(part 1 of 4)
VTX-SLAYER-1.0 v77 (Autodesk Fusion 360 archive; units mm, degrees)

design "VTX-SLAYER-1.0" references "nut", "M2 screw size FLAT WASHER", "M2 x 0.4mm Thread 20mm LONG SOCKET HEAD CAP SCREW", "runcam_phoenix_2", "M3 x 0.5mm Thread 16mm LONG SOCKET HEAD CAP SCREW", "motor", "M2 x 0.4mm Thread 5mm LONG SOCKET HEAD CAP SCREW", "prop", "M3 x 0.5mm Thread 8mm LONG SOCKET HEAD CAP SCREW", "M2 x 0.4mm Thread HEX NUT", "M2 x 0.4mm Thread 6mm LONG SOCKET HEAD CAP SCREW"
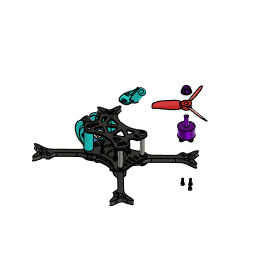
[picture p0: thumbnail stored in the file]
parameter "d278" = 4.1
parameter "d427" = 3.1
parameter "d437" = 4.2
parameter "d451" = 2.2
parameter "d614" = 15
parameter "d1109" = 4
parameter "d1134" = 12.8 (= "25.6 mm / 2.0")
canvas "Ansichtsbereich"
sketch "Skizze1" plane through (0, 0, 0) normal (0, 0, 1) x axis (1, 0, 0)
  line L1 (5.8693, -34.9991) -> (5.8693, -25.0204)
  line L2 (-57.0019, 8.0109) -> (-57.5891, 7.9385)
  line L3 (-57.259, 10.0951) -> (-57.8463, 10.0227)
  line L4 (-53.0046, 14.7338) -> (-53.0363, 15.3314)
  line L5 (-50.9075, 14.8451) -> (-50.9392, 15.4427)
  line L6 (-45.7643, 10.7703) -> (-46.3634, 10.7515)
  line L7 (-46.2975, 8.6525) -> (-45.6984, 8.6714)
  line L8 (0.8693, -39.9991) -> (-14.9589, -39.9991)
  line L9 (5.2623, -39.9991) -> (0.8693, -39.9991)
  line L10 (5.8693, -39.9991) -> (5.2623, -39.9991)
  line L11 (5.8693, -34.9991) -> (5.8693, -39.9991)
  line L12 (15.8693, -49.9991) -> (15.873, -49.9991)
  line L13 (15.8693, -29.9991) -> (15.873, -29.9991)
  line L14 (-7.6307, -25.3947) -> (-7.6307, -34.4991)
  curve K1 (-7.6307, -25.3947) -> (-10.9746, -20.0338)
  curve K2 (-12.5574, -19.204) -> (-9.3918, -20.8636)
  curve K3 (-7.6307, -25.7698) -> (-7.6307, -25.0196)
  line L15 (-20.2292, -25.643) -> (-53.829, 7.2456)
  line L16 (-49.632, 11.5333) -> (-16.0322, -21.3552)
  curve K4 (-25.1132, -12.4665) -> (-14.076, -18.1856)
  curve K5 (-42.6895, -3.6581) -> (-58.4159, 4.3179)
  curve K6 (-39.5769, 1.6911) -> (-43.0511, 12.8356)
  curve K7 (-39.0355, 1.1612) -> (-40.1182, 2.221)
  curve K8 (-42.3474, 12.2194) -> (-43.7548, 13.4517)
  curve K9 (-41.833, -4.4965) -> (-43.5461, -2.8197)
  curve K10 (-57.742, 4.1664) -> (-59.0898, 4.4693)
  curve K11 (-26.2747, -11.3295) -> (-23.9517, -13.6034)
  curve K12 (-14.6037, -17.8994) -> (-13.5483, -18.4717)
  curve K13 (-26.9801, -19.0351) -> (-22.3176, -27.7327)
  curve K14 (-22.9195, -27.2509) -> (-21.7157, -28.2145)
  curve K15 (-27.6566, -18.3729) -> (-26.3035, -19.6973)
  line L17 (-65.0703, 8.0734) -> (-57.1305, 9.053)
  line L18 (-52.3801, 22.7782) -> (-51.956, 14.7895)
  curve K16 (5.8693, -25.0204) -> (-14.076, -18.1856)
  curve K17 (-12.5184, -19.0318) -> (-15.6337, -17.3393)
  curve K18 (10.1662, -25.0241) -> (1.5724, -25.0168)
  curve K19 (-22.3176, -27.7327) -> (-10.6307, -34.4991)
  curve K20 (-10.6307, -32.2321) -> (-10.6307, -36.7662)
  curve K21 (-17.5546, -29.5) -> (-14.0454, -29.5)
  curve K22 (-23.5931, -26.7897) -> (-21.042, -28.6757)
  curve K23 (-43.0511, 12.8356) -> (-47.6742, 16.5575)
  curve K24 (-47, 15.6) -> (-48.3483, 17.515)
  curve K25 (-42.3474, 12.2194) -> (-43.7548, 13.4517)
  curve K26 (-47.6742, 16.5575) -> (-58.4159, 4.3179)
  curve K27 (-62.844, 5.395) -> (-53.9878, 3.2408)
  curve K28 (-65.2846, 9.8103) -> (-64.856, 6.3366)
  curve K29 (-54.7508, 15.3088) -> (-57.8176, 12.0705)
  curve K30 (-50.6326, 22.871) -> (-54.1277, 22.6854)
  curve K31 (-46.4995, 14.804) -> (-48.8488, 18.311)
  circle C1 centre (-51.7305, 9.3895) radius 2.7
  circle C2 centre (-57.7177, 8.9806) radius 1.05
  circle C3 centre (-57.1305, 9.053) radius 1.05
  circle C4 centre (-51.9878, 15.3871) radius 1.05
  circle C5 centre (-51.956, 14.7895) radius 1.05
  circle C6 centre (-46.3305, 9.702) radius 1.05
  circle C7 centre (-45.7313, 9.7208) radius 1.05
  circle C8 centre (-18.1307, -23.4991) radius 1.55
  circle C9 centre (-4.1307, -29.9991) radius 1.05
  circle C10 centre (15.873, -29.9991) radius 1.05
  circle C11 centre (29.8693, -23.4991) radius 1.55
  circle C12 centre (5.8693, -39.9991) radius 5
  circle C13 centre (-18.1307, -56.4991) radius 1.55
  circle C14 centre (15.873, -49.9991) radius 1.05
  circle C15 centre (29.8693, -56.4991) radius 1.55
  circle C16 centre (-4.1307, -49.9991) radius 1.05
  circle C17 centre (-9.1307, -34.4991) radius 1.5
  circle C18 centre (-18.1307, -23.4991) radius 3
  circle C19 centre (-51.7305, 9.3895) radius 3
  point P12 (-57.0019, 8.0109)
  point P11 (-57.5891, 7.9385)
  point P14 (-57.259, 10.0951)
  point P13 (-57.8463, 10.0227)
  point P15 (-53.0363, 15.3314)
  point P18 (-50.9075, 14.8451)
  point P19 (-46.3634, 10.7515)
  point P20 (-45.7643, 10.7703)
  point P21 (-45.6984, 8.6714)
  point P22 (-46.2975, 8.6525)
  point P17 (-50.9392, 15.4427)
  point P16 (-53.0046, 14.7338)
  point P29 (0.8693, -39.9991)
  point P30 (5.8693, -34.9991)
  point P24 (-18.1307, -23.4991)
  point P27 (29.8693, -23.4991)
  point P28 (5.8693, -39.9991)
  point P32 (5.8693, -39.9991)
  point P34 (15.873, -49.9991)
  point P36 (15.873, -49.9991)
  point P26 (15.873, -29.9991)
  point P38 (15.873, -29.9991)
  point P41 (-10.6307, -34.4991)
  point P43 (-9.1307, -34.4991)
  point P44 (-7.6307, -34.4991)
  point P46 (-10.9746, -20.0338)
  point P45 (-7.6307, -25.3947)
  point P49 (-7.6307, -25.7698)
  point P52 (-53.829, 7.2456)
  point P53 (-20.2292, -25.643)
  point P54 (-16.0322, -21.3552)
  point P55 (-49.632, 11.5333)
  point P23 (-14.076, -18.1856)
  point P56 (-14.076, -18.1856)
  point P57 (-25.1132, -12.4665)
  point P58 (-42.6895, -3.6581)
  point P59 (-39.5769, 1.6911)
  point P61 (-39.0355, 1.1612)
  point P86 (-43.0511, 12.8356)
  point P65 (-41.833, -4.4965)
  point P85 (-58.4159, 4.3179)
  point P69 (-26.2747, -11.3295)
  point P73 (-26.9801, -19.0351)
  point P72 (-22.3176, -27.7327)
  point P77 (-27.6566, -18.3729)
  point P6 (-57.1305, 9.053)
  point P81 (-57.1305, 9.053)
  point P8 (-51.956, 14.7895)
  point P83 (-51.956, 14.7895)
  point P7 (-51.9878, 15.3871)
  point P5 (-57.7177, 8.9806)
  point P78 (-65.0703, 8.0734)
  point P82 (-65.0703, 8.0734)
  point P80 (-52.3801, 22.7782)
  point P84 (-52.3801, 22.7782)
  point P4 (5.8693, -25.0204)
  point P42 (-15.8, -29.5)
  point P97 (-47.6742, 16.5575)
  point P79 (-56.2842, 13.6897)
  point P112 (-10.9746, -20.0338)
  point P70 (-13.5483, -18.4717)
  point P62 (-43.7548, 13.4517)
  point P100 (-43.7548, 13.4517)
  point P25 (-4.1307, -29.9991)
  point P39 (15.8693, -29.9991)
  point P2 (-51.7305, 9.3895)
  point P9 (-46.3305, 9.702)
  point P37 (15.8693, -49.9991)
  point P40 (-4.1307, -49.9991)
  point P3 (-14.9589, -39.9991)
  point P104 (-64.856, 6.3366)
  point P105 (-65.2846, 9.8103)
  point P108 (-54.1277, 22.6854)
  point P109 (-50.6326, 22.871)
  horizontal L8
  perpendicular L1 L8
  coincident C3 P12
  tangent C3 L2
  coincident C2 P11
  tangent C2 L2
  coincident C3 P14
  tangent C3 L3
  coincident C2 P13
  tangent C2 L3
  coincident C4 P15
  tangent C4 L4
  tangent C5 L4
  coincident C5 P18
  tangent C5 L5
  tangent C4 L5
  coincident C6 P19
  tangent C6 L6
  coincident C7 P20
  tangent C7 L6
  coincident C7 P21
  tangent C7 L7
  coincident C6 P22
  tangent C6 L7
  coincident C4 P17
  coincident C5 P16
  coincident C12 P29
  coincident C12 P30
  perpendicular L1 L9
  horizontal P24 P27
  parallel L9 L10
  perpendicular L9 L11
  coincident P28 P32
  symmetric C8 L8 C13
  symmetric C10 L8 C14
  symmetric C11 L8 C15
  coincident P34 P36
  coincident P26 P38
  parallel L12 L13
  symmetric C9 L8 C16
  coincident P41 C17
  horizontal P41 P43
  coincident C17 P44
  tangent C17 L14
  vertical L14
  midpoint P46 K2
  midpoint P45 K3
  coincident L14 P49
  concentric C8 C18
  concentric C1 C19
  coincident C19 P52
  coincident C18 P53
  tangent C18 L15
  coincident C18 P54
  coincident C19 P55
  tangent C19 L16
  tangent C19 L15
  tangent C18 L16
  coincident P23 P56
  coincident L16 P57
  coincident L15 P58
  coincident L16 P59
  midpoint P59 K7
  coincident L16 P61
  parallel L16 K7
  midpoint K8 P86
  midpoint P58 K9
  coincident L15 P65
  parallel L15 K9
  midpoint K10 P85
  midpoint P57 K11
  coincident L16 P69
  midpoint P56 K12
  coincident L15 P73
  midpoint P72 K14
  midpoint P73 K15
  coincident L15 P77
  parallel L15 K15
  coincident P6 P81
  coincident P8 P83
  coincident P7 L18
  coincident P5 L17
  coincident P78 P82
  coincident P80 P84
  midpoint P23 K17
  midpoint P4 K18
  midpoint P41 K20
  midpoint P42 K21
  midpoint P72 K22
  midpoint P97 K24
  midpoint P86 K25
  midpoint P85 K27
  midpoint P78 K28
  midpoint P79 K29
  midpoint P80 K30
  midpoint P97 K31
  coincident P46 P112
  coincident P70 K16
  perpendicular L17 K28
  perpendicular L18 K30
  coincident P62 P100
  dimension "d4" diameter C1 = 5.4
  dimension "d8" diameter C2 = 2.1
  dimension "d9" diameter C3 = 2.1
  dimension "d10" diameter C4 = 2.1
  dimension "d11" diameter C5 = 2.1
  dimension "d12" diameter C6 = 2.1
  dimension "d13" diameter C7 = 2.1
  dimension "d14" diameter C8 = 3.1
  dimension "d16" diameter C9 = 2.1
  dimension "d17" diameter C10 = 2.1 (= "d16")
  dimension "d20" diameter C11 = 3.1 (= "d14")
  dimension "d23" distance P25 P39 = 20
  dimension "d27" diameter C12 = 10
  dimension "d50" distance P4 P28 = 14.9787
  dimension "d58" distance P24 P27 = 48 (= "d103 * 2")
  dimension "d102" distance L1 P25 = 10
  dimension "d103" distance L1 P24 = 24
  dimension "d145" distance P2 P6 = 5.4
  dimension "d146" distance P2 P9 = 5.4
  dimension "d148" distance P2 P8 = 5.4
  dimension "d265" distance P2 L1 = 57.5997
  dimension "d266" distance P2 L8 = 49.3886
  dimension "d267" distance P24 L8 = 16.5
  dimension "d272" distance P25 L8 = 10
  dimension "d273" distance P37 P39 = 20
  dimension "d274" distance P37 P40 = 20
  dimension "d520" diameter C17 = 3
  dimension "d521" distance P28 P43 = 15
  dimension "d522" distance L8 P43 = 5.5
  dimension "d523" distance P3 P29 = 15.8282
  dimension "d669" diameter C18 = 6
  dimension "d670" diameter C19 = 6
  dimension "d709" distance P83 P84 = 8
  dimension "d710" distance P81 P82 = 8
  dimension "d1085" distance P104 P105 = 3.5
  dimension "d1086" distance P108 P109 = 3.5
extrude "Extrusion4" new body sketch "Skizze1" profile of C1 K23 C2 C3 C4 C5 C6 C7 L2 L3 L4 L5 L6 L7 C8 K19 C17 L14 K1 L15 L16 K4 K5 K6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 along normal blind 5 bodies "arm-fr"
work_plane "Arbeitsebene3" RotateAngle -90
work_plane "Arbeitsebene4" RotateAngle 90
mirror "Spiegeln6" mirrorStitchTolerance 0.1 bodies "arm-rr"
mirror "Spiegeln7" mirrorStitchTolerance 0.1 bodies "arm-fl", "arm-rl"
sketch "Skizze43" plane through (0, 0, 5) normal (0, 0, 1) x axis (-1, 0, 0)
  line L1 (53.0363, -15.3314) -> (53.0046, -14.7338)
  line L2 (50.9075, -14.8451) -> (50.9392, -15.4427)
  line L3 (45.7643, -10.7703) -> (46.3634, -10.7515)
  line L4 (46.2975, -8.6525) -> (45.6984, -8.6714)
  line L5 (57.5891, -7.9385) -> (57.0019, -8.0109)
  line L6 (57.259, -10.0951) -> (57.8463, -10.0227)
  curve K1 (10.6307, 34.4991) -> (22.3176, 27.7327)
  line L7 (53.0046, 94.732) -> (53.0363, 95.3296)
  line L8 (50.9392, 95.441) -> (50.9075, 94.8433)
  line L9 (45.6984, 88.6696) -> (46.2975, 88.6508)
  line L10 (46.3634, 90.7497) -> (45.7643, 90.7686)
  line L11 (57.0019, 88.0092) -> (57.5891, 87.9367)
  line L12 (57.8463, 90.0209) -> (57.259, 90.0934)
  curve K2 (10.6307, 45.4991) -> (22.3176, 52.2655)
  line L13 (-64.7748, 95.3296) -> (-64.7431, 94.732)
  line L14 (-62.646, 94.8433) -> (-62.6778, 95.441)
  line L15 (-57.5028, 90.7686) -> (-58.1019, 90.7497)
  line L16 (-58.0361, 88.6508) -> (-57.4369, 88.6696)
  line L17 (-69.3276, 87.9367) -> (-68.7404, 88.0092)
  line L18 (-68.9976, 90.0934) -> (-69.5848, 90.0209)
  curve K3 (-22.3693, 45.4991) -> (-34.0561, 52.2655)
  line L19 (-64.7431, -14.7338) -> (-64.7748, -15.3314)
  line L20 (-62.6778, -15.4427) -> (-62.646, -14.8451)
  line L21 (-57.4369, -8.6714) -> (-58.0361, -8.6525)
  line L22 (-58.1019, -10.7515) -> (-57.5028, -10.7703)
  line L23 (-68.7404, -8.0109) -> (-69.3276, -7.9385)
  line L24 (-69.5848, -10.0227) -> (-68.9976, -10.0951)
  curve K4 (-22.3693, 34.4991) -> (-34.0561, 27.7327)
  line L25 (-2.454, 39.9991) -> (16.5436, 39.9991)
  line L26 (-5.8693, 35.997) -> (-5.8693, 24.0226)
  line L27 (-45, 39.9991) -> (35, 39.9991)
  line L28 (-5.8693, 61) -> (-5.8693, 13.9501)
  curve K5 (14.9589, 39.9991) -> (13.0937, 29.8846)
  curve K6 (5.0594, 23.381) -> (7.6307, 25.3947)
  curve K7 (7.6307, 23.731) -> (7.6307, 27.0584)
  curve K8 (3.3466, 23.9517) -> (6.7722, 22.8102)
  curve K9 (14.9589, 42.2662) -> (14.9589, 37.732)
  curve K10 (14.715, 29.209) -> (11.4725, 30.5602)
  curve K11 (15.7694, 31.8891) -> (15.1694, 30.2891)
  line L29 (-5.8693, 33.7991) -> (3.3307, 33.7991)
  line L30 (7.6307, 25.3947) -> (7.6307, 34.4991)
  curve K12 (9.6778, 20.9358) -> (7.6307, 25.3947)
  line L31 (-19.3693, 54.6035) -> (-19.3693, 45.4991)
  curve K13 (-21.4163, 59.0625) -> (-19.3693, 54.6035)
  line L32 (-19.3693, 34.4991) -> (-19.3693, 25.3947)
  line L33 (7.6307, 45.4991) -> (7.6307, 54.6035)
  curve K14 (10.9746, 20.0338) -> (9.6778, 20.9358)
  curve K15 (-22.7131, 59.9644) -> (-21.4163, 59.0625)
  curve K16 (9.6778, 59.0625) -> (7.6307, 54.6035)
  curve K17 (-21.4163, 20.9358) -> (-19.3693, 25.3947)
  curve K18 (10.9746, 59.9644) -> (9.6778, 59.0625)
  curve K19 (-22.7131, 20.0338) -> (-21.4163, 20.9358)
  curve K20 (43.0511, -12.8356) -> (39.5769, -1.6911)
  curve K21 (25.1132, 12.4665) -> (14.076, 18.1856)
  line L34 (39.5769, -1.6911) -> (25.1132, 12.4665)
  curve K22 (43.0511, 92.8338) -> (39.5769, 81.6893)
  line L35 (25.1132, 67.5318) -> (39.5769, 81.6893)
  curve K23 (25.1132, 67.5318) -> (14.076, 61.8127)
  curve K24 (47.6742, 96.5557) -> (43.0511, 92.8338)
  curve K25 (-54.7896, 92.8338) -> (-51.3154, 81.6893)
  curve K26 (-36.8517, 67.5318) -> (-25.8145, 61.8127)
  line L36 (-51.3154, 81.6893) -> (-36.8517, 67.5318)
  curve K27 (-54.7896, -12.8356) -> (-51.3154, -1.6911)
  line L37 (-36.8517, 12.4665) -> (-51.3154, -1.6911)
  curve K28 (-36.8517, 12.4665) -> (-25.8145, 18.1856)
  curve K29 (-59.4127, -16.5575) -> (-54.7896, -12.8356)
  curve K30 (42.6895, 3.6581) -> (58.4159, -4.3179)
  line L38 (26.9801, 19.0351) -> (42.6895, 3.6581)
  curve K31 (22.3176, 27.7327) -> (26.9801, 19.0351)
  curve K32 (22.3176, 52.2655) -> (26.9801, 60.9632)
  line L39 (42.6895, 76.3401) -> (26.9801, 60.9632)
  curve K33 (42.6895, 76.3401) -> (58.4159, 84.3161)
  curve K34 (-59.4127, 96.5557) -> (-54.7896, 92.8338)
  curve K35 (-54.4281, 76.3401) -> (-70.1544, 84.3161)
  line L40 (-38.7186, 60.9632) -> (-54.4281, 76.3401)
  curve K36 (-34.0561, 52.2655) -> (-38.7186, 60.9632)
  curve K37 (-34.0561, 27.7327) -> (-38.7186, 19.0351)
  line L41 (-54.4281, 3.6581) -> (-38.7186, 19.0351)
  curve K38 (-54.4281, 3.6581) -> (-70.1544, -4.3179)
  curve K39 (52.3801, -22.7782) -> (47.6742, -16.5575)
  curve K40 (65.0703, -8.0734) -> (52.3801, -22.7782)
  curve K41 (52.3801, 102.7764) -> (47.6742, 96.5557)
  curve K42 (-64.1186, 102.7764) -> (-59.4127, 96.5557)
  curve K43 (-76.8088, 88.0717) -> (-64.1186, 102.7764)
  curve K44 (-64.1186, -22.7782) -> (-59.4127, -16.5575)
  curve K45 (65.0703, 88.0717) -> (52.3801, 102.7764)
  curve K46 (-76.8088, -8.0734) -> (-64.1186, -22.7782)
  curve K47 (-5.8693, 25.0204) -> (14.076, 18.1856)
  curve K48 (58.4159, -4.3179) -> (65.0703, -8.0734)
  curve K49 (58.4159, 84.3161) -> (65.0703, 88.0717)
  curve K50 (-70.1544, 84.3161) -> (-76.8088, 88.0717)
  curve K51 (-70.1544, -4.3179) -> (-76.8088, -8.0734)
  curve K52 (14.076, 18.1856) -> (10.9746, 20.0338)
  curve K53 (47.6742, -16.5575) -> (43.0511, -12.8356)
  curve K54 (14.076, 61.8127) -> (10.9746, 59.9644)
  curve K55 (-25.8145, 18.1856) -> (-22.7131, 20.0338)
  curve K56 (-25.8145, 61.8127) -> (-22.7131, 59.9644)
  arc A1 centre (51.9878, -15.3871) radius 1.05 clockwise from (53.0363, -15.3314) to (50.9392, -15.4427)
  arc A2 centre (51.956, -14.7895) radius 1.05 clockwise from (50.9075, -14.8451) to (53.0046, -14.7338)
  circle C1 centre (18.1307, 23.4991) radius 1.55
  arc A3 centre (46.3305, -9.702) radius 1.05 clockwise from (46.2975, -8.6525) to (46.3634, -10.7515)
  arc A4 centre (45.7313, -9.7208) radius 1.05 clockwise from (45.7643, -10.7703) to (45.6984, -8.6714)
  arc A5 centre (57.7177, -8.9806) radius 1.05 clockwise from (57.5891, -7.9385) to (57.8463, -10.0227)
  arc A6 centre (57.1305, -9.053) radius 1.05 clockwise from (57.259, -10.0951) to (57.0019, -8.0109)
  circle C2 centre (51.7305, -9.3895) radius 2.7
  arc A7 centre (9.1307, 34.4991) radius 1.5 clockwise from (7.6307, 34.4991) to (10.6307, 34.4991)
  arc A8 centre (51.956, 94.7877) radius 1.05 clockwise from (53.0046, 94.732) to (50.9075, 94.8433)
  arc A9 centre (51.9878, 95.3853) radius 1.05 clockwise from (50.9392, 95.441) to (53.0363, 95.3296)
  circle C3 centre (18.1307, 56.4991) radius 1.55
  arc A10 centre (46.3305, 89.7003) radius 1.05 clockwise from (46.3634, 90.7497) to (46.2975, 88.6508)
  arc A11 centre (45.7313, 89.7191) radius 1.05 clockwise from (45.6984, 88.6696) to (45.7643, 90.7686)
  arc A12 centre (57.1305, 89.0513) radius 1.05 clockwise from (57.0019, 88.0092) to (57.259, 90.0934)
  arc A13 centre (57.7177, 88.9788) radius 1.05 clockwise from (57.8463, 90.0209) to (57.5891, 87.9367)
  circle C4 centre (51.7305, 89.3877) radius 2.7
  arc A14 centre (9.1307, 45.4991) radius 1.5 clockwise from (10.6307, 45.4991) to (7.6307, 45.4991)
  arc A15 centre (-63.7263, 95.3853) radius 1.05 clockwise from (-64.7748, 95.3296) to (-62.6778, 95.441)
  arc A16 centre (-63.6946, 94.7877) radius 1.05 clockwise from (-62.646, 94.8433) to (-64.7431, 94.732)
  circle C5 centre (-29.8693, 56.4991) radius 1.55
  arc A17 centre (-58.069, 89.7003) radius 1.05 clockwise from (-58.0361, 88.6508) to (-58.1019, 90.7497)
  arc A18 centre (-57.4698, 89.7191) radius 1.05 clockwise from (-57.5028, 90.7686) to (-57.4369, 88.6696)
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  point P107 (13.0937, 29.8846)
  point P111 (-5.8693, 39.9991)
  point P109 (7.6307, 25.3947)
  point P110 (5.0594, 23.381)
  point P108 (15.4694, 31.0891)
  point P128 (-5.8693, 33.7991)
  point P114 (7.6307, 27.0584)
  parallel L25 L27
  perpendicular L27 L28
  coincident K1 P107
  coincident L28 P111
  coincident L27 P111
  midpoint P109 K7
  midpoint P110 K8
  midpoint P107 K10
  midpoint P108 K11
  horizontal L29
  coincident L26 P128
  coincident L28 P128
  parallel L28 K9
  coincident P109 L30
  coincident P114 L30
  dimension "d356" diameter = 4.2
  dimension "d363" diameter = 3.1
  dimension "d503" distance P111 P128 = 6.2
extrude "Extrusion55" new body sketch "Skizze43" against normal blind 2 bodies "m-center"
mirror "Spiegeln20" mirrorStitchTolerance 0.1
mirror "Spiegeln21" mirrorStitchTolerance 0.1
sketch "Skizze4" plane through (0, 0, 0) normal (0, 0, -1) x axis (1, 0, 0)
  line L1 (-45.6984, -8.6714) -> (-46.2975, -8.6525)
  line L2 (-46.3634, -10.7515) -> (-45.7643, -10.7703)
  line L3 (-53.0046, -14.7338) -> (-53.0363, -15.3314)
  line L4 (-50.9392, -15.4427) -> (-50.9075, -14.8451)
  line L5 (-57.0019, -8.0109) -> (-57.5891, -7.9385)
  line L6 (-57.8463, -10.0227) -> (-57.259, -10.0951)
  line L7 (5.8693, 34.9991) -> (5.8693, 39.9991)
  line L8 (5.8693, 34.9991) -> (5.8693, 25.0204)
  curve K1 (-22.3176, 27.7327) -> (-10.6307, 34.4991)
  curve K2 (-13.2943, 29.8104) -> (-14.9589, 39.9991)
  curve K3 (-13.0937, 29.8846) -> (-13.2943, 29.8104)
  curve K4 (-5.4893, 23.275) -> (-7.6307, 25.3947)
  line L9 (-34.1307, 39.9991) -> (5.8693, 39.9991)
  line L10 (-34.1307, 46.2008) -> (-34.1307, 39.9991)
  line L11 (-12.5862, 69.6661) -> (-34.1307, 46.2008)
  line L12 (-57.5891, 87.9367) -> (-57.0019, 88.0092)
  line L13 (-57.259, 90.0934) -> (-57.8463, 90.0209)
  line L14 (-53.0363, 95.3296) -> (-53.0046, 94.732)
  line L15 (-50.9075, 94.8433) -> (-50.9392, 95.441)
  line L16 (-45.7643, 90.7686) -> (-46.3634, 90.7497)
  line L17 (-46.2975, 88.6508) -> (-45.6984, 88.6696)
  curve K5 (-22.3176, 52.2655) -> (-10.6307, 45.4991)
  curve K6 (-1.6863, 55.6114) -> (-9.6778, 59.0625)
  curve K7 (0.3253, 55.2725) -> (-3.698, 55.9502)
  curve K8 (-3.0083, 56.2858) -> (-3.1917, 58.5142)
  curve K9 (-8.5538, 58.2617) -> (-10.8018, 59.8633)
  curve K10 (-2.18, 58.2549) -> (-5.9502, 58.4922)
  line L18 (5.8693, 35.997) -> (5.8693, 24.0226)
  line L19 (68.7404, 88.0092) -> (69.3276, 87.9367)
  line L20 (69.5848, 90.0209) -> (68.9976, 90.0934)
  line L21 (64.7431, 94.732) -> (64.7748, 95.3296)
  line L22 (62.6778, 95.441) -> (62.646, 94.8433)
  line L23 (57.4369, 88.6696) -> (58.0361, 88.6508)
  line L24 (58.1019, 90.7497) -> (57.5028, 90.7686)
  curve K11 (34.0561, 52.2655) -> (22.3693, 45.4991)
  curve K12 (26.6564, 39.9983) -> (33.3763, 51.7943)
  curve K13 (26.6564, 38.371) -> (26.6564, 41.6256)
  curve K14 (32.9215, 51.5105) -> (33.8311, 52.0782)
  line L25 (40, 39.9991) -> (5.8693, 39.9991)
  line L26 (-29.6307, 42.9991) -> (-13.1687, 42.9991)
  line L27 (-13.1687, 48.9991) -> (-25.1307, 48.9991)
  line L28 (-13.1687, 42.9991) -> (-13.1687, 48.9991)
  line L29 (-20.1687, 42.9991) -> (-29.6307, 42.9991)
  line L30 (-14.6007, 50.4991) -> (-25.1307, 50.4991)
  line L31 (-12.0137, 44.4991) -> (-29.6307, 44.4991)
  line L32 (-12.0137, 41.4991) -> (-29.6307, 41.4991)
  line L33 (-14.6007, 47.4991) -> (-25.1307, 47.4991)
  curve K15 (-7.6307, 25.3947) -> (-9.6778, 20.9358)
  line L34 (-7.6307, 34.4991) -> (-7.6307, 25.3947)
  line L35 (-7.6307, 25.3947) -> (-7.6307, 34.4991)
  line L36 (-7.6307, 54.6035) -> (-7.6307, 45.4991)
  curve K16 (19.3693, 54.6035) -> (21.4163, 59.0625)
  line L37 (19.3693, 45.4991) -> (19.3693, 54.6035)
  line L38 (24.3247, 69.6661) -> (45.8693, 46.2008)
  curve K17 (-7.6307, 54.6035) -> (-9.6778, 59.0625)
  curve K18 (13.4249, 55.6114) -> (21.4163, 59.0625)
  curve K19 (20.2923, 58.2617) -> (22.5404, 59.8633)
  curve K20 (13.9185, 58.2549) -> (17.6888, 58.4922)
  curve K21 (14.7469, 56.2858) -> (14.9302, 58.5142)
  curve K22 (11.4132, 55.2725) -> (15.4365, 55.9502)
  line L39 (22.3617, 39.9991) -> (22.3693, 45.4966)
  curve K23 (-9.6778, 20.9358) -> (-10.9746, 20.0338)
  curve K24 (21.4163, 59.0625) -> (22.7131, 59.9644)
  curve K25 (-39.5769, -1.6911) -> (-43.0511, -12.8356)
  line L40 (-25.1132, 12.4665) -> (-39.5769, -1.6911)
  curve K26 (-25.1132, 12.4665) -> (-14.076, 18.1856)
  curve K27 (-39.5769, 81.6893) -> (-43.0511, 92.8338)
  curve K28 (-9.6778, 59.0625) -> (-10.9746, 59.9644)
  curve K29 (-25.1132, 67.5318) -> (-14.076, 61.8127)
  line L41 (-39.5769, 81.6893) -> (-25.1132, 67.5318)
  curve K30 (51.3154, 81.6893) -> (54.7896, 92.8338)
  line L42 (36.8517, 67.5318) -> (51.3154, 81.6893)
  curve K31 (36.8517, 67.5318) -> (25.8145, 61.8127)
  curve K32 (-26.9801, 19.0351) -> (-22.3176, 27.7327)
  line L43 (-42.6895, 3.6581) -> (-26.9801, 19.0351)
  curve K33 (-42.6895, 3.6581) -> (-58.4159, -4.3179)
  curve K34 (-42.6895, 76.3401) -> (-58.4159, 84.3161)
  line L44 (-26.9801, 60.9632) -> (-42.6895, 76.3401)
  curve K35 (-26.9801, 60.9632) -> (-22.3176, 52.2655)
  curve K36 (38.7186, 60.9632) -> (34.0561, 52.2655)
  line L45 (54.4281, 76.3401) -> (38.7186, 60.9632)
  curve K37 (54.4281, 76.3401) -> (70.1544, 84.3161)
  line L46 (10.0693, 50.9491) -> (1.6693, 50.9491)
  line L47 (10.0693, 47.4491) -> (1.6693, 47.4491)
  curve K38 (-10.6307, 34.4991) -> (-13.0937, 29.8846)
  curve K39 (17.2278, 23.275) -> (19.3693, 25.3947)
  line L48 (19.3693, 34.4991) -> (19.3693, 25.3947)
  curve K40 (22.3693, 34.4991) -> (24.8323, 29.8846)
  curve K41 (24.8323, 29.8846) -> (25.0329, 29.8104)
  curve K42 (25.0329, 29.8104) -> (26.6974, 39.9991)
  curve K43 (25.0329, 50.1878) -> (26.6974, 39.9991)
  curve K44 (24.8323, 50.1137) -> (25.0329, 50.1878)
  curve K45 (22.3693, 45.4991) -> (24.8323, 50.1137)
  line L49 (19.3693, 54.6035) -> (19.3693, 45.4991)
  curve K46 (17.2278, 56.7233) -> (19.3693, 54.6035)
  curve K47 (-5.4893, 56.7233) -> (-7.6307, 54.6035)
  line L50 (-7.6307, 45.4991) -> (-7.6307, 54.6035)
  curve K48 (-10.6307, 45.4991) -> (-13.0937, 50.1137)
  curve K49 (-13.0937, 50.1137) -> (-13.2943, 50.1878)
  curve K50 (-13.2943, 50.1878) -> (-14.9589, 39.9991)
  curve K51 (-52.3801, -22.7782) -> (-65.0703, -8.0734)
  curve K52 (-47.6742, -16.5575) -> (-52.3801, -22.7782)
  curve K53 (-47.6742, 96.5557) -> (-52.3801, 102.7764)
  curve K54 (64.1186, 102.7764) -> (76.8088, 88.0717)
  curve K55 (59.4127, 96.5557) -> (64.1186, 102.7764)
  curve K56 (-43.0511, 92.8338) -> (-47.6742, 96.5557)
  curve K57 (-52.3801, 102.7764) -> (-65.0703, 88.0717)
  curve K58 (54.7896, 92.8338) -> (59.4127, 96.5557)
  curve K59 (5.8693, 54.9778) -> (17.2278, 56.7233)
  curve K60 (5.8693, 54.9778) -> (-5.4893, 56.7233)
  curve K61 (5.8693, 25.0204) -> (-5.4893, 23.275)
  curve K62 (5.8693, 25.0204) -> (17.2278, 23.275)
  curve K63 (-65.0703, -8.0734) -> (-58.4159, -4.3179)
  curve K64 (-65.0703, 88.0717) -> (-58.4159, 84.3161)
  curve K65 (76.8088, 88.0717) -> (70.1544, 84.3161)
  curve K66 (-10.9746, 20.0338) -> (-14.076, 18.1856)
  curve K67 (-10.9746, 59.9644) -> (-14.076, 61.8127)
  curve K68 (22.7131, 59.9644) -> (25.8145, 61.8127)
  arc A1 centre (-46.3305, -9.702) radius 1.05 clockwise from (-46.3634, -10.7515) to (-46.2975, -8.6525)
  arc A2 centre (-45.7313, -9.7208) radius 1.05 clockwise from (-45.6984, -8.6714) to (-45.7643, -10.7703)
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  point P73 (-1.6863, 55.6114)
  point P72 (-3.1, 57.4)
  point P70 (-9.6778, 59.0625)
  point P71 (-4.0651, 58.3735)
  point P110 (33.3763, 51.7943)
  point P22 (5.8693, 39.9991)
  point P115 (5.8693, 39.9991)
  point P118 (-29.6307, 42.9991)
  point P124 (-29.6307, 42.9991)
  point P125 (-12.0137, 42.9991)
  point P119 (-25.1307, 48.9991)
  point P126 (-25.1307, 48.9991)
  point P127 (-14.6007, 48.9991)
  point P136 (5.8693, 39.9991)
  point P41 (5.8693, 39.9991)
  point P44 (-34.1307, 46.2008)
  point P146 (45.8693, 46.2008)
  point P45 (-12.5862, 69.6661)
  point P147 (24.3247, 69.6661)
  point P152 (21.4163, 59.0625)
  point P153 (15.8036, 58.3735)
  point P154 (14.8385, 57.4)
  point P155 (13.4249, 55.6114)
  point P74 (-3.698, 55.9502)
  point P162 (15.4365, 55.9502)
  point P75 (0.3253, 55.2725)
  point P163 (11.4132, 55.2725)
  point P76 (-3.1917, 58.5142)
  point P160 (14.9302, 58.5142)
  point P77 (-3.0083, 56.2858)
  point P161 (14.7469, 56.2858)
  point P78 (-10.8018, 59.8633)
  point P156 (22.5404, 59.8633)
  point P79 (-8.5538, 58.2617)
  point P157 (20.2923, 58.2617)
  point P80 (-5.9502, 58.4922)
  point P158 (17.6888, 58.4922)
  point P81 (-2.18, 58.2549)
  point P159 (13.9185, 58.2549)
  point P165 (22.3617, 39.9991)
  point P117 (-13.1687, 42.9991)
  point P120 (-13.1687, 48.9991)
  point P43 (-34.1307, 39.9991)
  point P189 (1.6693, 49.1991)
  point P190 (10.0693, 49.1991)
  perpendicular L9 L10
  midpoint P73 K7
  midpoint P72 K8
  midpoint P70 K9
  midpoint P71 K10
  parallel L7 L10
  midpoint P110 K14
  coincident P22 P115
  perpendicular L7 L25
  horizontal L26
  horizontal L27
  vertical L28
  horizontal L29
  coincident P118 P124
  coincident L26 P125
  coincident P119 P126
  coincident L27 P127
  parallel L31 L32
  coincident P22 P136
  coincident P41 P136
  symmetric P44 L18 P146
  symmetric P45 L18 P147
  coincident P70 K17
  symmetric P70 L18 P152
  symmetric P71 L18 P153
  symmetric P72 L18 P154
  symmetric P73 L18 P155
  symmetric P74 L18 P162
  symmetric P75 L18 P163
  symmetric P76 L18 P160
  symmetric P77 L18 P161
  symmetric P78 L18 P156
  symmetric P79 L18 P157
  symmetric P80 L18 P158
  symmetric P81 L18 P159
  parallel L18 K13
  coincident L25 P165
  coincident K11 P110
  horizontal L46
  parallel L46 L47
  dimension "d397" distance P117 P120 = 6
  dimension "d399" distance L9 L26 = 3
  dimension "d472" diameter = 3
  dimension "d481" diameter = 3
  dimension "d482" diameter = 3
  dimension "d483" diameter = 3
  dimension "d510" diameter = 6
  dimension "d532" distance P41 P43 = 40
  dimension "d544" distance L10 P126 = 9
  dimension "d545" distance L10 P124 = 4.5
  dimension "d682" diameter = 3.5
  dimension "d683" diameter = 3.5
  dimension "d684" distance P115 P189 = 4.2
  dimension "d685" distance P115 P190 = 4.2
  dimension "d686" distance L9 P189 = 9.2
  dimension "d687" distance L25 P190 = 9.2
  dimension "d688" diameter = 4.2
extrude "Extrusion56" new body sketch "Skizze4" along normal blind 2 bodies "m-bottom"
fillet "Fillet26" radius 6
mirror "Spiegeln22" mirrorStitchTolerance 0.1
work_axis "Arbeitsachse" sketch "Skizze43"
fillet "Fillet32" radius 5
fillet "Fillet44" radius 5
copy_paste_bodies "CopyPasteBodies9"
move "Move19"
move "Move20" RotateAngle 180
sketch "topplate" plane through (0, 0, 7) normal (0, 0, 1) x axis (-1, 0, 0)
  curve K1 (9.811, 20.8371) -> (10.9746, 20.0338)
  line L1 (-26.3392, 50.4991) -> (-34.3693, 50.4991)
  line L2 (-34.3693, 47.4991) -> (-26.3392, 47.4991)
  line L3 (-23.7522, 44.4991) -> (-34.3693, 44.4991)
  line L4 (-34.3693, 41.4991) -> (-23.7522, 41.4991)
  line L5 (-2.8693, 49.9991) -> (-8.8693, 49.9991)
  line L6 (-8.8693, 45.9991) -> (-2.8693, 45.9991)
  line L7 (-2.8693, 33.9991) -> (-8.8693, 33.9991)
  line L8 (-8.8693, 29.9991) -> (-2.8693, 29.9991)
  line L9 (-23.7522, 38.4991) -> (-34.3693, 38.4991)
  line L10 (-34.3693, 35.4991) -> (-23.7522, 35.4991)
  line L11 (-26.3392, 32.4991) -> (-34.3693, 32.4991)
  line L12 (-34.3693, 29.4991) -> (-26.3392, 29.4991)
  curve K2 (14.9178, 39.9991) -> (14.9887, 41.536)
  curve K3 (14.9178, 39.9991) -> (14.9887, 38.4622)
  curve K4 (14.991, 38.4401) -> (21.2218, 28.4813)
  curve K5 (14.991, 41.5582) -> (21.2218, 51.5169)
  line L13 (21.0607, 60.4361) -> (21.7601, 59.6743)
  line L14 (-44.2889, 47.922) -> (-32.7992, 60.4361)
  line L15 (-45.8693, 36.1341) -> (-45.8693, 43.8641)
  line L16 (-32.7992, 19.5622) -> (-44.2889, 32.0762)
  line L17 (21.7601, 20.324) -> (21.0607, 19.5622)
  line L18 (-23.7522, 44.4991) -> (-41.3693, 44.4991)
  line L19 (-41.3693, 41.4991) -> (-23.7522, 41.4991)
  line L20 (-26.3392, 50.4991) -> (-36.8693, 50.4991)
  line L21 (-36.8693, 47.4991) -> (-26.3392, 47.4991)
  line L22 (-26.3392, 32.4991) -> (-36.8693, 32.4991)
  line L23 (-36.8693, 29.4991) -> (-26.3392, 29.4991)
  line L24 (-23.7522, 38.4991) -> (-41.3693, 38.4991)
  line L25 (-41.3693, 35.4991) -> (-23.7522, 35.4991)
  curve K6 (-21.4163, 59.0625) -> (-22.7131, 59.9644)
  curve K7 (-21.4163, 20.9358) -> (-22.7131, 20.0338)
  curve K8 (23.3399, 24.4614) -> (21.2218, 28.4813)
  curve K9 (21.2218, 51.5169) -> (23.3399, 55.5369)
  curve K10 (1.7709, 55.6283) -> (9.811, 59.1611)
  curve K11 (0.8783, 55.4553) -> (2.6635, 55.8012)
  curve K12 (9.0903, 58.6539) -> (10.5317, 59.6683)
  line L26 (-2.454, 39.9991) -> (16.5436, 39.9991)
  curve K13 (1.7709, 24.37) -> (9.811, 20.8371)
  curve K14 (9.0903, 21.3444) -> (10.5317, 20.3299)
  curve K15 (0.8783, 24.5429) -> (2.6635, 24.197)
  line L27 (-5.8693, 35.997) -> (-5.8693, 24.0226)
  curve K16 (-13.5094, 24.37) -> (-21.5495, 20.8371)
  curve K17 (-20.8288, 21.3444) -> (-22.2702, 20.3299)
  curve K18 (-12.6168, 24.5429) -> (-14.402, 24.197)
  curve K19 (-13.5094, 55.6283) -> (-21.5495, 59.1611)
  curve K20 (-20.8288, 58.6539) -> (-22.2702, 59.6683)
  curve K21 (-12.6168, 55.4553) -> (-14.402, 55.8012)
  curve K22 (-5.8693, 25.0204) -> (-13.4249, 24.3869)
  curve K23 (-5.8693, 25.0204) -> (1.6863, 24.3869)
  curve K24 (-5.8693, 54.9778) -> (1.6863, 55.6114)
  curve K25 (-5.8693, 54.9778) -> (-13.4249, 55.6114)
  curve K26 (14.9178, 39.9991) -> (14.991, 38.4401)
  curve K27 (14.9178, 39.9991) -> (14.991, 41.5582)
  curve K28 (13.7829, 61.6537) -> (21.0607, 60.4361)
  curve K29 (10.9746, 59.9644) -> (13.7829, 61.6537)
  curve K30 (-22.7131, 59.9644) -> (-25.5215, 61.6537)
  curve K31 (-32.7992, 60.4361) -> (-25.5215, 61.6537)
  curve K32 (-32.7992, 19.5622) -> (-25.5215, 18.3445)
  curve K33 (-22.7131, 20.0338) -> (-25.5215, 18.3445)
  curve K34 (10.9746, 20.0338) -> (13.7829, 18.3445)
  curve K35 (13.7829, 18.3445) -> (21.0607, 19.5622)
  curve K36 (9.6778, 59.0625) -> (10.9746, 59.9644)
  curve K37 (1.7709, 55.6283) -> (9.6778, 59.0625)
  curve K38 (1.6863, 55.6114) -> (1.7709, 55.6283)
  curve K39 (-13.4249, 55.6114) -> (-13.5094, 55.6283)
  curve K40 (-13.5094, 55.6283) -> (-21.4163, 59.0625)
  curve K41 (-13.5094, 24.37) -> (-21.4163, 20.9358)
  curve K42 (-13.4249, 24.3869) -> (-13.5094, 24.37)
  curve K43 (1.6863, 24.3869) -> (1.7709, 24.37)
  curve K44 (1.7709, 24.37) -> (9.6778, 20.9358)
  curve K45 (9.6778, 20.9358) -> (10.9746, 20.0338)
  arc A1 centre (-34.3693, 48.9991) radius 1.5 clockwise from (-34.3693, 47.4991) to (-34.3693, 50.4991)
  arc A2 centre (-26.3392, 48.9991) radius 1.5 clockwise from (-26.3392, 50.4991) to (-26.3392, 47.4991)
  arc A3 centre (-34.3693, 42.9991) radius 1.5 clockwise from (-34.3693, 41.4991) to (-34.3693, 44.4991)
  arc A4 centre (-23.7522, 42.9991) radius 1.5 clockwise from (-23.7522, 44.4991) to (-23.7522, 41.4991)
  circle C1 centre (-29.8693, 56.4991) radius 1.55
  arc A5 centre (-8.8693, 47.9991) radius 2 clockwise from (-8.8693, 45.9991) to (-8.8693, 49.9991)
  arc A6 centre (-2.8693, 47.9991) radius 2 clockwise from (-2.8693, 49.9991) to (-2.8693, 45.9991)
  arc A7 centre (-8.8693, 31.9991) radius 2 clockwise from (-8.8693, 29.9991) to (-8.8693, 33.9991)
  arc A8 centre (-2.8693, 31.9991) radius 2 clockwise from (-2.8693, 33.9991) to (-2.8693, 29.9991)
  circle C2 centre (-29.8693, 23.4991) radius 1.55
  arc A9 centre (-34.3693, 36.9991) radius 1.5 clockwise from (-34.3693, 35.4991) to (-34.3693, 38.4991)
  arc A10 centre (-23.7522, 36.9991) radius 1.5 clockwise from (-23.7522, 38.4991) to (-23.7522, 35.4991)
  arc A11 centre (-34.3693, 30.9991) radius 1.5 clockwise from (-34.3693, 29.4991) to (-34.3693, 32.4991)
  arc A12 centre (-26.3392, 30.9991) radius 1.5 clockwise from (-26.3392, 32.4991) to (-26.3392, 29.4991)
  circle C3 centre (-5.8693, 39.9991) radius 3
  circle C4 centre (18.1307, 23.4991) radius 2.55
  circle C5 centre (18.1307, 56.4991) radius 2.55
  circle C6 centre (-29.8693, 56.4991) radius 2.55
  circle C7 centre (-29.8693, 23.4991) radius 2.55
  circle C8 centre (4.1307, 29.9991) radius 1.05
  circle C9 centre (4.1307, 49.9991) radius 1.05
  circle C10 centre (-15.8693, 49.9991) radius 1.05
  circle C11 centre (-15.8693, 29.9991) radius 1.05
  circle C12 centre (-5.8693, 39.9991) radius 1.55
  circle C13 centre (-5.8693, 39.9991) radius 2.55
  arc A13 centre (-39.8693, 43.8641) radius 6 clockwise from (-45.8693, 43.8641) to (-44.2889, 47.922)
  arc A14 centre (-39.8693, 36.1341) radius 6 clockwise from (-44.2889, 32.0762) to (-45.8693, 36.1341)
  circle C14 centre (-5.8693, 39.9991) radius 3
  arc A15 centre (-41.3693, 42.9991) radius 1.5 clockwise from (-41.3693, 41.4991) to (-41.3693, 44.4991)
  arc A16 centre (-23.7522, 42.9991) radius 1.5 clockwise from (-23.7522, 44.4991) to (-23.7522, 41.4991)
  arc A17 centre (-36.8693, 48.9991) radius 1.5 clockwise from (-36.8693, 47.4991) to (-36.8693, 50.4991)
  arc A18 centre (-26.3392, 48.9991) radius 1.5 clockwise from (-26.3392, 50.4991) to (-26.3392, 47.4991)
  arc A19 centre (-36.8693, 30.9991) radius 1.5 clockwise from (-36.8693, 29.4991) to (-36.8693, 32.4991)
  arc A20 centre (-26.3392, 30.9991) radius 1.5 clockwise from (-26.3392, 32.4991) to (-26.3392, 29.4991)
  arc A21 centre (-41.3693, 36.9991) radius 1.5 clockwise from (-41.3693, 35.4991) to (-41.3693, 38.4991)
  arc A22 centre (-23.7522, 36.9991) radius 1.5 clockwise from (-23.7522, 38.4991) to (-23.7522, 35.4991)
  circle C15 centre (18.1307, 23.4991) radius 2.25
  circle C16 centre (-29.8693, 23.4991) radius 2.25
  circle C17 centre (18.1307, 56.4991) radius 2.25
  circle C18 centre (-29.8693, 56.4991) radius 2.25
  circle C19 centre (-5.8693, 39.9991) radius 2.25
  arc A23 centre (17.3404, 55.6164) radius 6 clockwise from (21.7601, 59.6743) to (23.3399, 55.5369)
  arc A24 centre (17.3404, 24.3819) radius 6 clockwise from (23.3399, 24.4614) to (21.7601, 20.324)
  circle C20 centre (-29.8693, 56.4991) radius 1.55
  circle C21 centre (-29.8693, 23.4991) radius 1.55
  arc A25 centre (4.1307, 29.9991) radius 2.1 clockwise from (4.1326, 32.0991) to (4.1326, 27.8991)
  arc A26 centre (4.1307, 49.9991) radius 2.1 clockwise from (4.1326, 52.0991) to (4.1326, 47.8991)
  arc A27 centre (4.1345, 29.9991) radius 2.1 clockwise from (4.1326, 27.8991) to (4.1326, 32.0991)
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  point P117 (1.7709, 55.6283)
  point P5 (9.811, 59.1611)
  point P124 (9.811, 20.8371)
  point P178 (1.7709, 24.37)
  point P118 (2.6635, 55.8012)
  point P127 (2.6635, 24.197)
  point P119 (0.8783, 55.4553)
  point P128 (0.8783, 24.5429)
  point P120 (10.5317, 59.6683)
  point P125 (10.5317, 20.3299)
  point P121 (9.0903, 58.6539)
  point P126 (9.0903, 21.3444)
  point P137 (-21.5495, 59.1611)
  point P138 (-13.5094, 55.6283)
  point P141 (-14.402, 55.8012)
  point P142 (-12.6168, 55.4553)
  point P139 (-22.2702, 59.6683)
  point P140 (-20.8288, 58.6539)
  point P131 (-21.5495, 20.8371)
  point P132 (-13.5094, 24.37)
  point P133 (-22.2702, 20.3299)
  point P134 (-20.8288, 21.3444)
  point P135 (-14.402, 24.197)
  point P136 (-12.6168, 24.5429)
  point P180 (1.7709, 24.37)
  concentric C1 C6
  concentric C2 C7
  concentric C3 C12
  concentric C12 C13
  concentric C4 C15
  concentric C2 C16
  concentric C1 C18
  concentric C13 C19
  midpoint P117 K11
  midpoint P5 K12
  symmetric P5 L26 P124
  symmetric P117 L26 P178
  symmetric P118 L26 P127
  symmetric P119 L26 P128
  symmetric P120 L26 P125
  symmetric P121 L26 P126
  symmetric P5 L27 P137
  symmetric P117 L27 P138
  symmetric P118 L27 P141
  symmetric P119 L27 P142
  symmetric P120 L27 P139
  symmetric P121 L27 P140
  symmetric P124 L27 P131
  symmetric L27 P132 P178
  symmetric P125 L27 P133
  symmetric P126 L27 P134
  symmetric P127 L27 P135
  symmetric P128 L27 P136
  coincident P178 P180
  dimension "d561" diameter C4 = 5.1
  dimension "d562" diameter C7 = 5.1 (= "d561")
  dimension "d563" diameter C6 = 5.1 (= "d561")
  dimension "d564" diameter C5 = 5.1 (= "d561")
  dimension "d565" diameter C8 = 2.1
  dimension "d566" diameter C11 = 2.1 (= "d565")
  dimension "d567" diameter C10 = 2.1 (= "d565")
  dimension "d568" diameter C9 = 2.1 (= "d565")
  dimension "d571" diameter C12 = 3.1
  dimension "d572" diameter C13 = 5.1 (= "d561")
  dimension "d641" diameter C15 = 4.5
  dimension "d642" diameter C16 = 4.5 (= "d641")
  dimension "d643" diameter C17 = 4.5 (= "d641")
  dimension "d644" diameter C18 = 4.5 (= "d641")
  dimension "d645" diameter C19 = 4.5 (= "d641")
extrude "Extrude73" add sketch "topplate" against normal blind 2
extrude "Extrude74" cut sketch "topplate" profile of C1 C2 C4 C5 C6 C7 C12 C13 C15 C16 C17 C18 C19 against normal blind 0.4
extrude "Extrude80" cut sketch "topplate" profile of C1 C2 C12 C15 C16 C17 C18 C19 against normal blind 1.1
extrude "Extrude81" cut sketch "topplate" profile of K10 L26 K13 K16 K19 against normal blind 2
sketch "top-chop" plane through (0, 0, 7) normal (0, 0, 1) x axis (-1, 0, 0)
  curve K1 (-34.0692, 39.9991) -> (-32.8495, 19.3496)
  curve K2 (-34.0384, 43.9982) -> (-34.1, 36)
  curve K3 (-34.2156, 20.7121) -> (-31.4834, 17.9871)
  line L1 (-2.454, 39.9991) -> (16.5436, 39.9991)
  curve K4 (-34.0692, 39.9991) -> (-32.8495, 60.6486)
  curve K5 (-34.2156, 59.2861) -> (-31.4834, 62.0111)
  curve K6 (-34.0384, 36) -> (-34.1, 43.9982)
  line L2 (-31.819, 50.4991) -> (-31.819, 29.4991)
  curve K7 (14.991, 38.4401) -> (21.2218, 28.4813)
  curve K8 (14.991, 41.5582) -> (21.2218, 51.5169)
  line L3 (21.0607, 60.4361) -> (21.7601, 59.6743)
  line L4 (-44.2889, 47.922) -> (-32.7992, 60.4361)
  line L5 (-45.8693, 36.1341) -> (-45.8693, 43.8641)
  line L6 (-32.7992, 19.5622) -> (-44.2889, 32.0762)
  line L7 (21.7601, 20.324) -> (21.0607, 19.5622)
  line L8 (-23.7522, 44.4991) -> (-41.3693, 44.4991)
  line L9 (-41.3693, 41.4991) -> (-23.7522, 41.4991)
  line L10 (-23.7522, 38.4991) -> (-41.3693, 38.4991)
  line L11 (-41.3693, 35.4991) -> (-23.7522, 35.4991)
  curve K9 (-21.4163, 59.0625) -> (-22.7131, 59.9644)
  curve K10 (-21.4163, 20.9358) -> (-22.7131, 20.0338)
  curve K11 (23.3399, 24.4614) -> (21.2218, 28.4813)
  curve K12 (21.2218, 51.5169) -> (23.3399, 55.5369)
  line L12 (-26.3392, 32.4991) -> (-34.3693, 32.4991)
  line L13 (-34.3693, 29.4991) -> (-26.3392, 29.4991)
  line L14 (-26.3392, 50.4991) -> (-34.3693, 50.4991)
  line L15 (-34.3693, 47.4991) -> (-26.3392, 47.4991)
  curve K13 (-5.8693, 25.0204) -> (1.6863, 24.3869)
  curve K14 (-5.8693, 54.9778) -> (1.6863, 55.6114)
  curve K15 (13.7829, 61.6537) -> (21.0607, 60.4361)
  curve K16 (10.9746, 59.9644) -> (13.7829, 61.6537)
  curve K17 (-5.8693, 54.9778) -> (-13.4249, 55.6114)
  curve K18 (-22.7131, 59.9644) -> (-25.5215, 61.6537)
  curve K19 (-32.7992, 60.4361) -> (-25.5215, 61.6537)
  curve K20 (-32.7992, 19.5622) -> (-25.5215, 18.3445)
  curve K21 (-22.7131, 20.0338) -> (-25.5215, 18.3445)
  curve K22 (-5.8693, 25.0204) -> (-13.4249, 24.3869)
  curve K23 (10.9746, 20.0338) -> (13.7829, 18.3445)
  curve K24 (13.7829, 18.3445) -> (21.0607, 19.5622)
  curve K25 (14.9178, 39.9991) -> (14.991, 38.4401)
  curve K26 (14.9178, 39.9991) -> (14.991, 41.5582)
  curve K27 (-21.2077, 58.9255) -> (-13.5094, 55.6283)
  curve K28 (-21.2077, 58.9255) -> (-21.4163, 59.0625)
  curve K29 (-21.2077, 21.0728) -> (-21.4163, 20.9358)
  curve K30 (-13.5094, 24.37) -> (-21.2077, 21.0728)
  curve K31 (-13.4249, 24.3869) -> (-13.5094, 24.37)
  curve K32 (1.6863, 24.3869) -> (1.7709, 24.37)
  curve K33 (9.4692, 21.0728) -> (1.7709, 24.37)
  curve K34 (9.4692, 21.0728) -> (9.6778, 20.9358)
  curve K35 (9.6778, 20.9358) -> (10.9746, 20.0338)
  curve K36 (9.6778, 59.0625) -> (10.9746, 59.9644)
  curve K37 (9.4692, 58.9255) -> (9.6778, 59.0625)
  curve K38 (1.7709, 55.6283) -> (9.4692, 58.9255)
  curve K39 (1.6863, 55.6114) -> (1.7709, 55.6283)
  curve K40 (-13.4249, 55.6114) -> (-13.5094, 55.6283)
  circle C1 centre (18.1307, 56.4991) radius 2.55
  circle C2 centre (18.1307, 23.4991) radius 2.55
  circle C3 centre (-29.8693, 56.4991) radius 2.55
  circle C4 centre (-29.8693, 23.4991) radius 2.55
  arc A1 centre (-39.8693, 43.8641) radius 6 clockwise from (-45.8693, 43.8641) to (-44.2889, 47.922)
  arc A2 centre (-39.8693, 36.1341) radius 6 clockwise from (-44.2889, 32.0762) to (-45.8693, 36.1341)
  arc A3 centre (-41.3693, 42.9991) radius 1.5 clockwise from (-41.3693, 41.4991) to (-41.3693, 44.4991)
  arc A4 centre (-23.7522, 42.9991) radius 1.5 clockwise from (-23.7522, 44.4991) to (-23.7522, 41.4991)
  arc A5 centre (-41.3693, 36.9991) radius 1.5 clockwise from (-41.3693, 35.4991) to (-41.3693, 38.4991)
  arc A6 centre (-23.7522, 36.9991) radius 1.5 clockwise from (-23.7522, 38.4991) to (-23.7522, 35.4991)
  arc A7 centre (17.3404, 55.6164) radius 6 clockwise from (21.7601, 59.6743) to (23.3399, 55.5369)
  arc A8 centre (17.3404, 24.3819) radius 6 clockwise from (23.3399, 24.4614) to (21.7601, 20.324)
  arc A9 centre (-26.3392, 30.9991) radius 1.5 clockwise from (-26.3392, 32.4991) to (-26.3392, 29.4991)
  arc A10 centre (-26.3392, 48.9991) radius 1.5 clockwise from (-26.3392, 50.4991) to (-26.3392, 47.4991)
  arc A11 centre (-34.3693, 30.9991) radius 1.5 clockwise from (-34.3693, 29.4991) to (-34.3693, 32.4991)
  arc A12 centre (-34.3693, 48.9991) radius 1.5 clockwise from (-34.3693, 47.4991) to (-34.3693, 50.4991)
  circle C5 centre (4.1307, 29.9991) radius 1.05
  circle C6 centre (-15.8693, 29.9991) radius 1.05
  circle C7 centre (4.1307, 49.9991) radius 1.05
  circle C8 centre (-15.8693, 49.9991) radius 1.05
  circle C9 centre (-5.8693, 39.9991) radius 2.55
  point P3 (-34.0692, 39.9991)
  point P2 (-32.8495, 19.3496)
  point P10 (-32.8495, 60.6486)
  point P11 (-34.0692, 39.9991)
  point P4 (-34.1, 36)
  point P14 (-34.1, 43.9982)
  point P5 (-34.0384, 43.9982)
  point P15 (-34.0384, 36)
  point P6 (-31.4834, 17.9871)
  point P12 (-31.4834, 62.0111)
  point P7 (-34.2156, 20.7121)
  point P13 (-34.2156, 59.2861)
  midpoint P3 K2
  midpoint P2 K3
  symmetric P2 L1 P10
  symmetric P3 L1 P11
  symmetric P4 L1 P14
  symmetric P5 L1 P15
  symmetric P6 L1 P12
  symmetric P7 L1 P13
extrude "Extrude76" cut sketch "top-chop" profile of K1 K4 L4 A1 L5 A2 L6 A3 L8 L9 A5 L10 L11 against normal blind 2
extrude "Extrude77" add sketch "top-chop" profile of K1 K4 L2 L8 L9 L10 L11 L12 L13 L14 L15 against normal blind 2
fillet "Fillet33" radius 1.5
component_insert "Komponente einfügen"
position "Position1"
